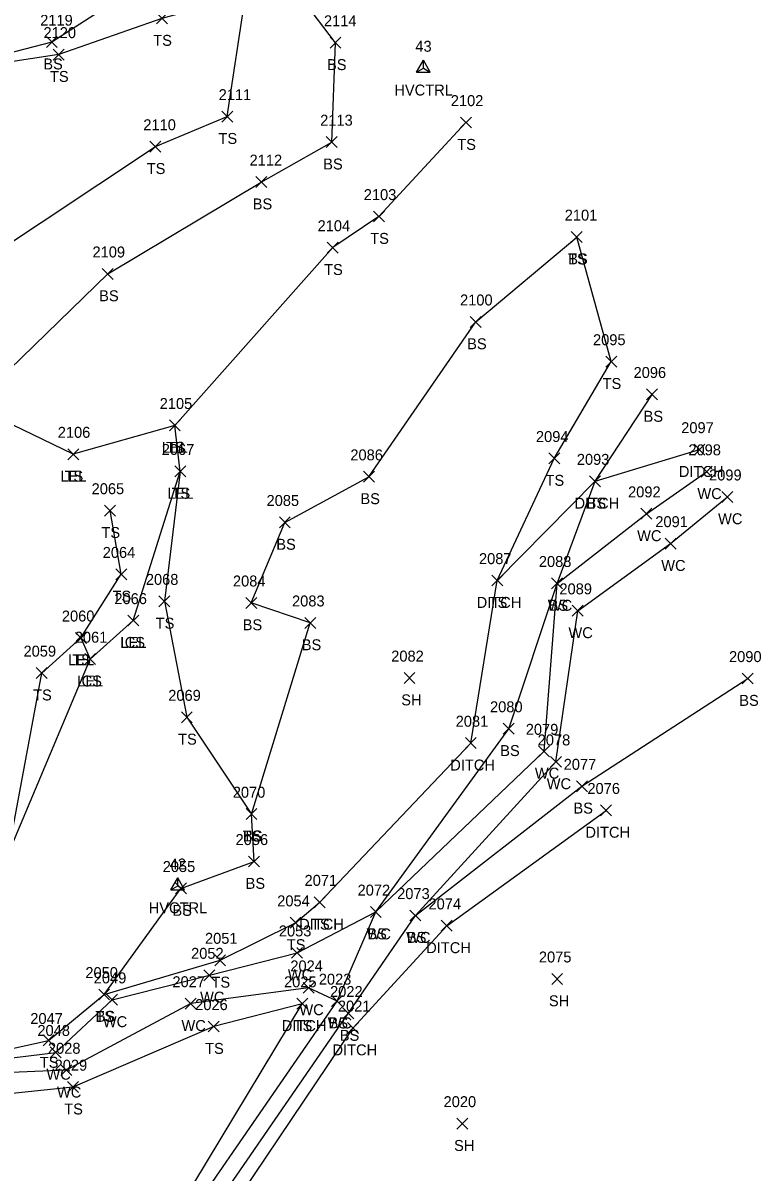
# Model space of a CAD drawing. Extents: x 1551995 to 1555700, y 777276 to 783130.
# Drawn here: x 1555125.8 to 1555260.7, y 778001.3 to 778211.4 of the extents above; entities that cross this region are included whole.
import ezdxf

# ---------------------------------------------------------------- set-up
doc = ezdxf.new("R2010")
doc.units = 0
for name, color, linetype in [('C_A', 7, 'Continuous'), ('C_I', 7, 'Continuous'), ('CPSM', 7, 'Continuous'), ('D_A', 7, 'Continuous'), ('D_I', 7, 'Continuous'), ('D_TIC', 7, 'Continuous'), ('DD', 7, 'Continuous'), ('L_A', 7, 'Continuous'), ('L_I', 7, 'Continuous'), ('L_TIC', 7, 'Continuous'), ('LARO', 7, 'Continuous'), ('LAWE', 7, 'Continuous'), ('LELB', 7, 'Continuous')]:
    doc.layers.add(name, color=color, linetype=linetype)

msp = doc.modelspace()

# ---------------------------------------------------------------- linework, layer by layer
at = {"layer": 'CPSM'}
for p, q in [((1555197.75, 778202.38), (1555199, 778204.54)), ((1555200.25, 778202.38), (1555199, 778204.54)), ((1555199, 778203.1), (1555199, 778204.54)), ((1555197.75, 778202.38), (1555199, 778203.1)), ((1555197.75, 778202.38), (1555200.25, 778202.38)), ((1555199, 778203.1), (1555199, 778203.1)), ((1555199, 778203.1), (1555200.25, 778202.38)), ((1555152.85, 778052.99), (1555154.1, 778055.16)), ((1555155.35, 778052.99), (1555154.1, 778055.16)), ((1555154.1, 778053.71), (1555154.1, 778055.16)), ((1555152.85, 778052.99), (1555154.1, 778053.71)), ((1555152.85, 778052.99), (1555155.35, 778052.99)), ((1555154.1, 778053.71), (1555154.1, 778053.71)), ((1555154.1, 778053.71), (1555155.35, 778052.99))]:
    msp.add_line(p, q, dxfattribs=at)
at = {"layer": 'D_TIC'}
for points in [[(1555248.46, 778132.42), (1555250.46, 778134.42)], [(1555250.46, 778132.42), (1555248.46, 778134.42)], [(1555229.38, 778126.63), (1555231.38, 778128.63)], [(1555231.38, 778126.63), (1555229.38, 778128.63)], [(1555211.5, 778108.5), (1555213.5, 778110.5)], [(1555213.5, 778108.5), (1555211.5, 778110.5)], [(1555206.67, 778078.79), (1555208.67, 778080.79)], [(1555208.67, 778078.79), (1555206.67, 778080.79)], [(1555231.38, 778066.51), (1555233.38, 778068.51)], [(1555233.38, 778066.51), (1555231.38, 778068.51)], [(1555179.05, 778049.72), (1555181.05, 778051.72)], [(1555181.05, 778049.72), (1555179.05, 778051.72)], [(1555202.27, 778045.42), (1555204.27, 778047.42)], [(1555204.27, 778045.42), (1555202.27, 778047.42)], [(1555175.87, 778031.18), (1555177.87, 778033.18)], [(1555177.87, 778031.18), (1555175.87, 778033.18)], [(1555185.15, 778026.75), (1555187.15, 778028.75)], [(1555187.15, 778026.75), (1555185.15, 778028.75)]]:
    msp.add_lwpolyline(points, dxfattribs=at)
at = {"layer": 'DD'}
for points in [[(1555180.05, 778050.72), (1555207.67, 778079.79), (1555212.5, 778109.5), (1555230.38, 778127.63), (1555249.46, 778133.42)], [(1555121.62, 777818), (1555123.19, 777819.14), (1555122.67, 777841.32), (1555131.63, 777887.47), (1555140.67, 777926.21), (1555150.07, 777955.34), (1555156.75, 777984.07), (1555186.15, 778027.75), (1555203.27, 778046.42), (1555232.38, 778067.51)], [(1555121.62, 777818), (1555117.52, 777846.44), (1555120.85, 777888.04), (1555130.77, 777928.13), (1555141.86, 777965.73), (1555149.54, 777986.93), (1555176.87, 778032.18)]]:
    msp.add_lwpolyline(points, dxfattribs=at)
at = {"layer": 'L_TIC'}
for points in [[(1555150.21, 778211.18), (1555152.21, 778213.18)], [(1555152.21, 778211.18), (1555150.21, 778213.18)], [(1555130.09, 778206.87), (1555132.09, 778208.87)], [(1555132.09, 778206.87), (1555130.09, 778208.87)], [(1555181.94, 778206.75), (1555183.94, 778208.75)], [(1555183.94, 778206.75), (1555181.94, 778208.75)], [(1555131.34, 778204.59), (1555133.34, 778206.59)], [(1555133.34, 778204.59), (1555131.34, 778206.59)], [(1555162.14, 778193.26), (1555164.14, 778195.26)], [(1555164.14, 778193.26), (1555162.14, 778195.26)], [(1555205.78, 778192.17), (1555207.78, 778194.17)], [(1555207.78, 778192.17), (1555205.78, 778194.17)], [(1555149.02, 778187.76), (1555151.02, 778189.76)], [(1555151.02, 778187.76), (1555149.02, 778189.76)], [(1555181.25, 778188.59), (1555183.25, 778190.59)], [(1555183.25, 778188.59), (1555181.25, 778190.59)], [(1555168.36, 778181.3), (1555170.36, 778183.3)], [(1555170.36, 778181.3), (1555168.36, 778183.3)], [(1555189.87, 778175), (1555191.87, 778177)], [(1555191.87, 778175), (1555189.87, 778177)], [(1555226.03, 778171.25), (1555228.03, 778173.25)], [(1555228.03, 778171.25), (1555226.03, 778173.25)], [(1555226.03, 778171.25), (1555228.03, 778173.25)], [(1555228.03, 778171.25), (1555226.03, 778173.25)], [(1555181.44, 778169.31), (1555183.44, 778171.31)], [(1555183.44, 778169.31), (1555181.44, 778171.31)], [(1555140.3, 778164.52), (1555142.3, 778166.52)], [(1555142.3, 778164.52), (1555140.3, 778166.52)], [(1555207.56, 778155.75), (1555209.56, 778157.75)], [(1555209.56, 778155.75), (1555207.56, 778157.75)], [(1555232.34, 778148.49), (1555234.34, 778150.49)], [(1555234.34, 778148.49), (1555232.34, 778150.49)], [(1555239.8, 778142.5), (1555241.8, 778144.5)], [(1555241.8, 778142.5), (1555239.8, 778144.5)], [(1555152.57, 778136.83), (1555154.57, 778138.83)], [(1555154.57, 778136.83), (1555152.57, 778138.83)], [(1555152.57, 778136.83), (1555154.57, 778138.83)], [(1555154.57, 778136.83), (1555152.57, 778138.83)], [(1555134, 778131.57), (1555136, 778133.57)], [(1555136, 778131.57), (1555134, 778133.57)], [(1555134, 778131.57), (1555136, 778133.57)], [(1555136, 778131.57), (1555134, 778133.57)], [(1555221.91, 778130.8), (1555223.91, 778132.8)], [(1555223.91, 778130.8), (1555221.91, 778132.8)], [(1555153.56, 778128.44), (1555155.56, 778130.44)], [(1555155.56, 778128.44), (1555153.56, 778130.44)], [(1555153.56, 778128.44), (1555155.56, 778130.44)], [(1555155.56, 778128.44), (1555153.56, 778130.44)], [(1555249.77, 778128.37), (1555251.77, 778130.37)], [(1555251.77, 778128.37), (1555249.77, 778130.37)], [(1555188.05, 778127.45), (1555190.05, 778129.45)], [(1555190.05, 778127.45), (1555188.05, 778129.45)], [(1555229.38, 778126.63), (1555231.38, 778128.63)], [(1555231.38, 778126.63), (1555229.38, 778128.63)], [(1555253.56, 778123.78), (1555255.56, 778125.78)], [(1555255.56, 778123.78), (1555253.56, 778125.78)], [(1555140.74, 778121.27), (1555142.74, 778123.27)], [(1555142.74, 778121.27), (1555140.74, 778123.27)], [(1555238.75, 778120.69), (1555240.75, 778122.69)], [(1555240.75, 778120.69), (1555238.75, 778122.69)], [(1555172.67, 778119.12), (1555174.67, 778121.12)], [(1555174.67, 778119.12), (1555172.67, 778121.12)], [(1555243.17, 778115.25), (1555245.17, 778117.25)], [(1555245.17, 778115.25), (1555243.17, 778117.25)], [(1555142.77, 778109.63), (1555144.77, 778111.63)], [(1555144.77, 778109.63), (1555142.77, 778111.63)], [(1555211.5, 778108.5), (1555213.5, 778110.5)], [(1555213.5, 778108.5), (1555211.5, 778110.5)], [(1555222.43, 778107.97), (1555224.43, 778109.97)], [(1555224.43, 778107.97), (1555222.43, 778109.97)], [(1555222.43, 778107.97), (1555224.43, 778109.97)], [(1555224.43, 778107.97), (1555222.43, 778109.97)], [(1555150.66, 778104.7), (1555152.66, 778106.7)], [(1555152.66, 778104.7), (1555150.66, 778106.7)], [(1555166.53, 778104.41), (1555168.53, 778106.41)], [(1555168.53, 778104.41), (1555166.53, 778106.41)], [(1555226.2, 778102.97), (1555228.2, 778104.97)], [(1555228.2, 778102.97), (1555226.2, 778104.97)], [(1555144.96, 778101.19), (1555146.96, 778103.19)], [(1555146.96, 778101.19), (1555144.96, 778103.19)], [(1555144.96, 778101.19), (1555146.96, 778103.19)], [(1555146.96, 778101.19), (1555144.96, 778103.19)], [(1555177.33, 778100.76), (1555179.33, 778102.76)], [(1555179.33, 778100.76), (1555177.33, 778102.76)], [(1555135.4, 778098.01), (1555137.4, 778100.01)], [(1555137.4, 778098.01), (1555135.4, 778100.01)], [(1555135.4, 778098.01), (1555137.4, 778100.01)], [(1555137.4, 778098.01), (1555135.4, 778100.01)], [(1555137.09, 778094.14), (1555139.09, 778096.14)], [(1555139.09, 778094.14), (1555137.09, 778096.14)], [(1555137.09, 778094.14), (1555139.09, 778096.14)], [(1555139.09, 778094.14), (1555137.09, 778096.14)], [(1555128.25, 778091.59), (1555130.25, 778093.59)], [(1555130.25, 778091.59), (1555128.25, 778093.59)], [(1555195.46, 778090.69), (1555197.46, 778092.69)], [(1555197.46, 778090.69), (1555195.46, 778092.69)], [(1555257.29, 778090.6), (1555259.29, 778092.6)], [(1555259.29, 778090.6), (1555257.29, 778092.6)], [(1555154.76, 778083.52), (1555156.76, 778085.52)], [(1555156.76, 778083.52), (1555154.76, 778085.52)], [(1555213.6, 778081.43), (1555215.6, 778083.43)], [(1555215.6, 778081.43), (1555213.6, 778083.43)], [(1555220.06, 778077.31), (1555222.06, 778079.31)], [(1555222.06, 778077.31), (1555220.06, 778079.31)], [(1555222.23, 778075.37), (1555224.23, 778077.37)], [(1555224.23, 778075.37), (1555222.23, 778077.37)], [(1555226.98, 778070.92), (1555228.98, 778072.92)], [(1555228.98, 778070.92), (1555226.98, 778072.92)], [(1555166.58, 778065.82), (1555168.58, 778067.82)], [(1555168.58, 778065.82), (1555166.58, 778067.82)], [(1555166.58, 778065.82), (1555168.58, 778067.82)], [(1555168.58, 778065.82), (1555166.58, 778067.82)], [(1555167.06, 778057.17), (1555169.06, 778059.17)], [(1555169.06, 778057.17), (1555167.06, 778059.17)], [(1555153.69, 778052.24), (1555155.69, 778054.24)], [(1555155.69, 778052.24), (1555153.69, 778054.24)], [(1555179.05, 778049.72), (1555181.05, 778051.72)], [(1555181.05, 778049.72), (1555179.05, 778051.72)], [(1555189.31, 778047.94), (1555191.31, 778049.94)], [(1555191.31, 778047.94), (1555189.31, 778049.94)], [(1555189.31, 778047.94), (1555191.31, 778049.94)], [(1555191.31, 778047.94), (1555189.31, 778049.94)], [(1555196.54, 778047.3), (1555198.54, 778049.3)], [(1555198.54, 778047.3), (1555196.54, 778049.3)], [(1555196.54, 778047.3), (1555198.54, 778049.3)], [(1555198.54, 778047.3), (1555196.54, 778049.3)], [(1555174.62, 778045.97), (1555176.62, 778047.97)], [(1555176.62, 778045.97), (1555174.62, 778047.97)], [(1555174.92, 778040.48), (1555176.92, 778042.48)], [(1555176.92, 778040.48), (1555174.92, 778042.48)], [(1555160.85, 778039.13), (1555162.85, 778041.13)], [(1555162.85, 778039.13), (1555160.85, 778041.13)], [(1555158.88, 778036.39), (1555160.88, 778038.39)], [(1555160.88, 778036.39), (1555158.88, 778038.39)], [(1555222.45, 778035.72), (1555224.45, 778037.72)], [(1555224.45, 778035.72), (1555222.45, 778037.72)], [(1555177.02, 778034.09), (1555179.02, 778036.09)], [(1555179.02, 778034.09), (1555177.02, 778036.09)], [(1555139.65, 778032.87), (1555141.65, 778034.87)], [(1555141.65, 778032.87), (1555139.65, 778034.87)], [(1555139.65, 778032.87), (1555141.65, 778034.87)], [(1555141.65, 778032.87), (1555139.65, 778034.87)], [(1555141.1, 778031.9), (1555143.1, 778033.9)], [(1555143.1, 778031.9), (1555141.1, 778033.9)], [(1555182.22, 778031.67), (1555184.22, 778033.67)], [(1555184.22, 778031.67), (1555182.22, 778033.67)], [(1555182.22, 778031.67), (1555184.22, 778033.67)], [(1555184.22, 778031.67), (1555182.22, 778033.67)], [(1555155.47, 778031.2), (1555157.47, 778033.2)], [(1555157.47, 778031.2), (1555155.47, 778033.2)], [(1555175.87, 778031.18), (1555177.87, 778033.18)], [(1555177.87, 778031.18), (1555175.87, 778033.18)], [(1555184.28, 778029.41), (1555186.28, 778031.41)], [(1555186.28, 778029.41), (1555184.28, 778031.41)], [(1555159.69, 778027.02), (1555161.69, 778029.02)], [(1555161.69, 778027.02), (1555159.69, 778029.02)], [(1555129.48, 778024.48), (1555131.48, 778026.48)], [(1555131.48, 778024.48), (1555129.48, 778026.48)], [(1555130.79, 778022.3), (1555132.79, 778024.3)], [(1555132.79, 778022.3), (1555130.79, 778024.3)], [(1555132.72, 778019.04), (1555134.72, 778021.04)], [(1555134.72, 778019.04), (1555132.72, 778021.04)], [(1555133.94, 778015.95), (1555135.94, 778017.95)], [(1555135.94, 778015.95), (1555133.94, 778017.95)], [(1555205.12, 778009.29), (1555207.12, 778011.29)], [(1555207.12, 778009.29), (1555205.12, 778011.29)]]:
    msp.add_lwpolyline(points, dxfattribs=at)
at = {"layer": 'LARO'}
msp.add_lwpolyline([(1555136.4, 778099.01), (1555138.09, 778095.14), (1555145.96, 778102.19), (1555154.56, 778129.44), (1555153.57, 778137.83), (1555135, 778132.57)], dxfattribs=at)
at = {"layer": 'LAWE'}
for points in [[(1554980.98, 778087.61), (1554986.81, 778080.45), (1554995.57, 778075.14), (1555006.25, 778070.66), (1555023.38, 778064.79), (1555066.22, 778057.61), (1555079.37, 778049.92), (1555092.5, 778039.7), (1555103.43, 778032.31), (1555111.16, 778025.28), (1555121.81, 778022.05), (1555131.79, 778023.3), (1555142.1, 778032.9), (1555159.88, 778037.39), (1555175.92, 778041.48), (1555190.31, 778048.94), (1555221.06, 778078.31), (1555223.43, 778108.97), (1555239.75, 778121.69), (1555250.77, 778129.37)], [(1555197.54, 778048.3), (1555223.23, 778076.37), (1555227.2, 778103.97), (1555244.17, 778116.25), (1555254.56, 778124.78)], [(1555183.22, 778032.67), (1555178.02, 778035.09), (1555156.47, 778032.2), (1555133.72, 778020.04), (1555110.79, 778019.04), (1555090.6, 778033.68), (1555075.24, 778046.42)]]:
    msp.add_lwpolyline(points, dxfattribs=at)
at = {"layer": 'LELB'}
for points in [[(1555135, 778132.57), (1555116.51, 778141.47), (1555118.7, 778168.03), (1555150.02, 778188.76), (1555163.14, 778194.26), (1555166.5, 778216.38), (1555151.21, 778212.18), (1555132.34, 778205.59), (1555108, 778201.88), (1555094.09, 778204.05), (1555093.66, 778246.97)], [(1555090.96, 778044.64), (1555101.27, 778057.41), (1555102.13, 778063.02), (1555118.39, 778106.13), (1555115.04, 778128.59), (1555116.51, 778141.47), (1555141.3, 778165.52), (1555169.36, 778182.3), (1555182.25, 778189.59), (1555182.94, 778207.75), (1555171.93, 778222.3), (1555147.47, 778218.47), (1555131.09, 778207.87), (1555108, 778201.88)], [(1555206.78, 778193.17), (1555190.87, 778176), (1555182.44, 778170.31), (1555153.57, 778137.83)], [(1555140.65, 778033.87), (1555154.69, 778053.24), (1555168.06, 778058.17), (1555167.58, 778066.82), (1555178.33, 778101.76), (1555167.53, 778105.41), (1555173.67, 778120.12), (1555189.05, 778128.45), (1555208.56, 778156.75), (1555227.03, 778172.25)], [(1555212.5, 778109.5), (1555222.91, 778131.8), (1555233.34, 778149.49), (1555227.03, 778172.25)], [(1555121.62, 777818), (1555119.52, 777846.53), (1555125.48, 777888.36), (1555134.7, 777929), (1555141.86, 777965.73), (1555151.31, 777986.37), (1555183.22, 778032.67), (1555190.31, 778048.94), (1555214.6, 778082.43), (1555223.43, 778108.97), (1555230.38, 778127.63), (1555240.8, 778143.5)], [(1555154.56, 778129.44), (1555151.66, 778105.7), (1555155.76, 778084.52), (1555167.58, 778066.82)], [(1555123.1, 778059.52), (1555129.25, 778092.59), (1555136.4, 778099.01), (1555143.77, 778110.63), (1555141.74, 778122.27)], [(1555112.51, 778027.47), (1555123.1, 778059.52), (1555138.09, 778095.14), (1555145.96, 778102.19)], [(1555123.19, 777819.14), (1555120.83, 777846.27), (1555129.65, 777888.2), (1555137.89, 777927.41), (1555148.54, 777956.04), (1555153.42, 777984.26), (1555185.28, 778030.41), (1555197.54, 778048.3), (1555227.98, 778071.92), (1555258.29, 778091.6)], [(1554988.34, 778085.79), (1554999.52, 778081.03), (1555010.57, 778076.63), (1555025.51, 778075.72), (1555050.35, 778074.06), (1555071.47, 778069.38), (1555082.88, 778057.69), (1555090.96, 778044.64), (1555104.92, 778035.73), (1555112.51, 778027.47), (1555122.17, 778023.62), (1555130.48, 778025.48), (1555140.65, 778033.87), (1555161.85, 778040.13), (1555175.62, 778046.97), (1555180.05, 778050.72)], [(1555176.87, 778032.18), (1555160.69, 778028.02), (1555134.94, 778016.95), (1555109.8, 778014.3), (1555088.71, 778025.22), (1555073.77, 778037.95)]]:
    msp.add_lwpolyline(points, dxfattribs=at)

# ---------------------------------------------------------------- texts
at = {"layer": 'C_A'}
for p in [(1555193.69, 778198.1), (1555148.79, 778048.71)]:
    msp.add_text('HVCTRL', height=2, dxfattribs=at).set_placement(p)
at = {"layer": 'C_I'}
for s, p in [('43', (1555197.53, 778206.1)), ('42', (1555152.63, 778056.71))]:
    msp.add_text(s, height=2, dxfattribs=at).set_placement(p)
at = {"layer": 'D_A'}
for p in [(1555245.69, 778128.42), (1555226.62, 778122.63), (1555208.74, 778104.5), (1555203.91, 778074.79), (1555228.61, 778062.51), (1555176.29, 778045.72), (1555199.51, 778041.42), (1555173.11, 778027.18), (1555182.38, 778022.75)]:
    msp.add_text('DITCH', height=2, dxfattribs=at).set_placement(p)
at = {"layer": 'D_I'}
for s, p in [('2097', (1555246.12, 778136.42)), ('2093', (1555227.04, 778130.63)), ('2087', (1555209.16, 778112.5)), ('2081', (1555204.9, 778082.79)), ('2076', (1555228.98, 778070.51)), ('2071', (1555177.28, 778053.72)), ('2074', (1555199.93, 778049.42)), ('2025', (1555173.53, 778035.18)), ('2021', (1555183.37, 778030.75))]:
    msp.add_text(s, height=2, dxfattribs=at).set_placement(p)
at = {"layer": 'L_A'}
for s, p in [('TS', (1555149.62, 778207.18)), ('BS', (1555129.53, 778202.87)), ('BS', (1555181.38, 778202.75)), ('TS', (1555130.75, 778200.59)), ('TS', (1555161.55, 778189.26)), ('TS', (1555205.19, 778188.17)), ('TS', (1555148.43, 778183.76)), ('BS', (1555180.69, 778184.59)), ('BS', (1555167.8, 778177.3)), ('TS', (1555189.28, 778171)), ('TS', (1555225.44, 778167.25)), ('BS', (1555225.47, 778167.25)), ('TS', (1555180.85, 778165.31)), ('BS', (1555139.74, 778160.52)), ('BS', (1555207, 778151.75)), ('TS', (1555231.75, 778144.49)), ('BS', (1555239.24, 778138.5)), ('LEL', (1555151.21, 778132.83)), ('TS', (1555151.98, 778132.83)), ('LEL', (1555132.64, 778127.57)), ('TS', (1555133.41, 778127.57)), ('TS', (1555221.32, 778126.8)), ('LEL', (1555152.2, 778124.44)), ('TS', (1555152.97, 778124.44)), ('WC', (1555249.08, 778124.37)), ('BS', (1555187.49, 778123.45)), ('BS', (1555228.82, 778122.63)), ('WC', (1555252.86, 778119.78)), ('TS', (1555140.15, 778117.27)), ('WC', (1555238.06, 778116.69)), ('BS', (1555172.11, 778115.12)), ('WC', (1555242.47, 778111.25)), ('TS', (1555142.18, 778105.63)), ('TS', (1555210.91, 778104.5)), ('WC', (1555221.74, 778103.97)), ('BS', (1555221.88, 778103.97)), ('TS', (1555150.07, 778100.7)), ('BS', (1555165.97, 778100.41)), ('WC', (1555225.51, 778098.97)), ('LEL', (1555143.6, 778097.19)), ('CS', (1555144.41, 778097.19)), ('BS', (1555176.77, 778096.76)), ('LEL', (1555134.04, 778094.01)), ('TS', (1555134.81, 778094.01)), ('LEL', (1555135.73, 778090.14)), ('CS', (1555136.53, 778090.14)), ('TS', (1555127.66, 778087.59)), ('SH', (1555194.95, 778086.69)), ('BS', (1555256.73, 778086.6)), ('TS', (1555154.17, 778079.52)), ('BS', (1555213.04, 778077.43)), ('WC', (1555219.37, 778073.31)), ('WC', (1555221.54, 778071.37)), ('BS', (1555226.42, 778066.92)), ('TS', (1555165.99, 778061.82)), ('BS', (1555166.02, 778061.82)), ('BS', (1555166.5, 778053.17)), ('BS', (1555153.13, 778048.24)), ('TS', (1555178.46, 778045.72)), ('TS', (1555174.03, 778041.97)), ('WC', (1555188.62, 778043.94)), ('BS', (1555188.75, 778043.94)), ('WC', (1555195.85, 778043.3)), ('BS', (1555195.98, 778043.3)), ('WC', (1555174.23, 778036.48)), ('TS', (1555160.26, 778035.13)), ('WC', (1555158.18, 778032.39)), ('SH', (1555221.94, 778031.72)), ('WC', (1555176.33, 778030.09)), ('TS', (1555139.06, 778028.87)), ('BS', (1555139.09, 778028.87)), ('WC', (1555140.41, 778027.9)), ('WC', (1555154.78, 778027.2)), ('TS', (1555175.28, 778027.18)), ('WC', (1555181.52, 778027.67)), ('BS', (1555181.66, 778027.67)), ('BS', (1555183.72, 778025.41)), ('TS', (1555159.1, 778023.02)), ('TS', (1555128.89, 778020.48)), ('WC', (1555130.1, 778018.3)), ('WC', (1555132.03, 778015.04)), ('TS', (1555133.35, 778011.95)), ('SH', (1555204.61, 778005.29))]:
    msp.add_text(s, height=2, dxfattribs=at).set_placement(p)
at = {"layer": 'L_I'}
for s, p in [('2119', (1555128.96, 778210.87)), ('2114', (1555180.82, 778210.75)), ('2120', (1555129.56, 778208.59)), ('2111', (1555161.58, 778197.26)), ('2102', (1555204.01, 778196.17)), ('2110', (1555147.81, 778191.76)), ('2113', (1555180.13, 778192.59)), ('2112', (1555167.23, 778185.3)), ('2103', (1555188.1, 778179)), ('2101', (1555224.83, 778175.25)), ('2101', (1555224.83, 778175.25)), ('2104', (1555179.66, 778173.31)), ('2109', (1555138.52, 778168.52)), ('2100', (1555205.7, 778159.75)), ('2095', (1555230, 778152.49)), ('2096', (1555237.41, 778146.5)), ('2105', (1555150.8, 778140.83)), ('2105', (1555150.8, 778140.83)), ('2106', (1555132.17, 778135.57)), ('2106', (1555132.17, 778135.57)), ('2094', (1555219.57, 778134.8)), ('2067', (1555151.18, 778132.44)), ('2067', (1555151.18, 778132.44)), ('2098', (1555247.43, 778132.37)), ('2086', (1555185.65, 778131.45)), ('2093', (1555227.04, 778130.63)), ('2099', (1555251.21, 778127.78)), ('2065', (1555138.36, 778125.27)), ('2092', (1555236.41, 778124.69)), ('2085', (1555170.33, 778123.12)), ('2091', (1555241.39, 778119.25)), ('2064', (1555140.39, 778113.63)), ('2087', (1555209.16, 778112.5)), ('2088', (1555220.1, 778111.97)), ('2088', (1555220.1, 778111.97)), ('2068', (1555148.27, 778108.7)), ('2084', (1555164.19, 778108.41)), ('2066', (1555142.52, 778105.19)), ('2066', (1555142.52, 778105.19)), ('2089', (1555223.86, 778106.97)), ('2083', (1555174.99, 778104.76)), ('2060', (1555132.92, 778102.01)), ('2060', (1555132.92, 778102.01)), ('2061', (1555135.28, 778098.14)), ('2061', (1555135.28, 778098.14)), ('2059', (1555125.91, 778095.59)), ('2082', (1555193.12, 778094.69)), ('2090', (1555254.86, 778094.6)), ('2069', (1555152.37, 778087.52)), ('2080', (1555211.18, 778085.43)), ('2079', (1555217.71, 778081.31)), ('2078', (1555219.89, 778079.37)), ('2077', (1555224.64, 778074.92)), ('2070', (1555164.16, 778069.82)), ('2070', (1555164.16, 778069.82)), ('2056', (1555164.67, 778061.17)), ('2055', (1555151.35, 778056.24)), ('2071', (1555177.28, 778053.72)), ('2072', (1555186.97, 778051.94)), ('2072', (1555186.97, 778051.94)), ('2073', (1555194.2, 778051.3)), ('2073', (1555194.2, 778051.3)), ('2054', (1555172.28, 778049.97)), ('2053', (1555172.58, 778044.48)), ('2051', (1555159.08, 778043.13)), ('2052', (1555156.54, 778040.39)), ('2024', (1555174.68, 778038.09)), ('2075', (1555220.11, 778039.72)), ('2050', (1555137.22, 778036.87)), ('2050', (1555137.22, 778036.87)), ('2049', (1555138.75, 778035.9)), ('2023', (1555179.88, 778035.67)), ('2023', (1555179.88, 778035.67)), ('2027', (1555153.13, 778035.2)), ('2025', (1555173.53, 778035.18)), ('2022', (1555181.94, 778033.41)), ('2026', (1555157.29, 778031.02)), ('2047', (1555127.15, 778028.48)), ('2048', (1555128.45, 778026.3)), ('2028', (1555130.38, 778023.04)), ('2029', (1555131.6, 778019.95)), ('2020', (1555202.69, 778013.29))]:
    msp.add_text(s, height=2, dxfattribs=at).set_placement(p)

doc.saveas('drawing.dxf')
